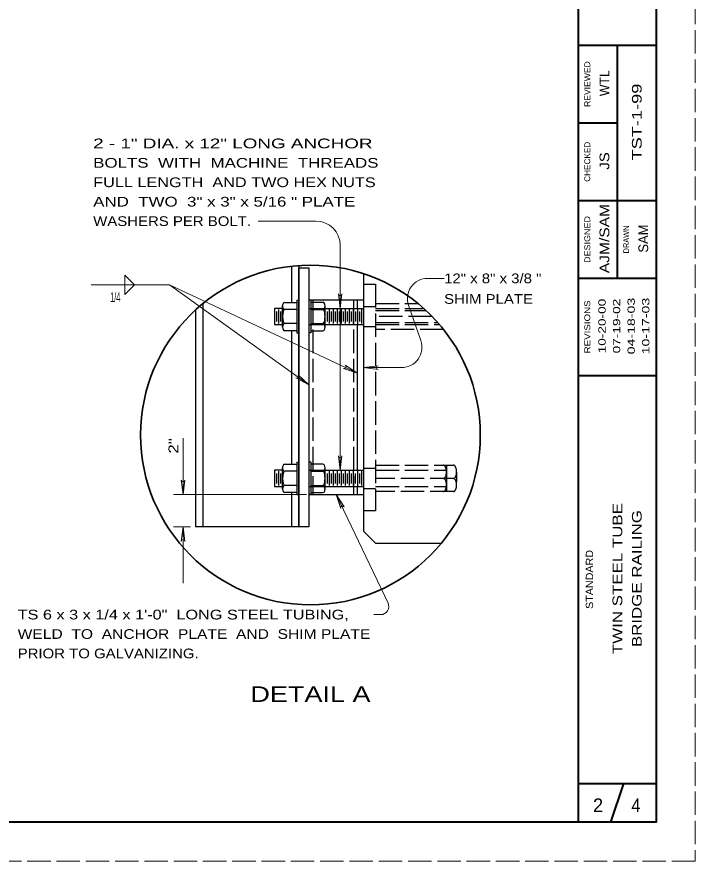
# Model space of a CAD drawing. Extents: x 1285 to 1427, y 1365 to 1427.
# Drawn here: x 1415.03 to 1426.67, y 1397.33 to 1411.82 of the extents above; entities that cross this region are included whole.
import ezdxf
from ezdxf.enums import TextEntityAlignment as Align

# ---------------------------------------------------------------- set-up
doc = ezdxf.new("R2010")
doc.units = 0
doc.header["$LTSCALE"] = 0.067
doc.linetypes.add('LONG_DASHED', pattern=[7.5, 6, -1.5])
for name, color, linetype, lineweight in [('1', 7, 'Continuous', 40), ('42', 7, 'Continuous', 25), ('44', 7, 'Continuous', 13)]:
    doc.layers.add(name, color=color, linetype=linetype, lineweight=lineweight)
doc.layers.add('41', color=7, linetype='Continuous')

msp = doc.modelspace()

# ---------------------------------------------------------------- linework, layer by layer
at = {"layer": '1'}
for p, q in [((1424.66667, 1398), (1424.66667, 1426)), ((1424.66667, 1411.33333), (1426, 1411.33333)), ((1425.33333, 1407.33333), (1425.33333, 1411.33333)), ((1424.66667, 1410), (1425.33333, 1410)), ((1424.66667, 1408.66667), (1426, 1408.66667)), ((1424.66667, 1407.33333), (1426, 1407.33333)), ((1424.66667, 1405.66667), (1426, 1405.66667)), ((1424.66667, 1398.66667), (1426, 1398.66667)), ((1425.22222, 1398), (1425.44444, 1398.66667))]:
    msp.add_line(p, q, dxfattribs=at)
at = {"layer": '1', "linetype": 'LONG_DASHED', "lineweight": 13}
msp.add_lwpolyline([(1381.33333, 1426.66667), (1426.66667, 1426.66667), (1426.66667, 1397.33333), (1381.33333, 1397.33333)], close=True, dxfattribs=at)
at = {"layer": '1'}
msp.add_lwpolyline([(1384, 1426), (1426, 1426), (1426, 1398), (1384, 1398)], close=True, dxfattribs=at)
at = {"layer": '42'}
for p, q in [((1419.74011, 1407.53967), (1419.74011, 1406.921)), ((1419.86656, 1407.54878), (1419.86656, 1403.067)), ((1418.22078, 1406.895), (1418.22078, 1403.067)), ((1419.62367, 1406.921), (1419.83211, 1406.921)), ((1419.83211, 1406.95567), (1419.83189, 1406.40033)), ((1419.83211, 1406.95567), (1419.86656, 1406.95567)), ((1420.97767, 1406.95589), (1420.04033, 1406.95589)), ((1420.07478, 1406.95567), (1420.04033, 1406.95567)), ((1420.07478, 1406.95567), (1420.075, 1406.40033)), ((1420.28322, 1406.921), (1420.07478, 1406.921)), ((1420.87367, 1406.81678), (1420.87367, 1406.95589)), ((1418.09433, 1406.78856), (1418.09433, 1403.067)), ((1419.48478, 1406.76478), (1419.48478, 1406.591)), ((1419.51944, 1406.79944), (1419.51944, 1406.55633)), ((1419.55411, 1406.76478), (1419.55411, 1406.591)), ((1419.589, 1406.49567), (1419.589, 1406.86033)), ((1419.83189, 1406.79944), (1419.62367, 1406.79944)), ((1420.075, 1406.79944), (1420.28322, 1406.79944)), ((1420.31789, 1406.49567), (1420.31789, 1406.86033)), ((1420.31789, 1406.81678), (1420.97767, 1406.81678)), ((1420.35278, 1406.76478), (1420.35278, 1406.591)), ((1420.38744, 1406.79944), (1420.38744, 1406.55633)), ((1420.42211, 1406.76478), (1420.42211, 1406.591)), ((1420.45678, 1406.79944), (1420.45678, 1406.55633)), ((1420.49144, 1406.76478), (1420.49144, 1406.591)), ((1420.52611, 1406.79944), (1420.52611, 1406.55633)), ((1420.56078, 1406.76478), (1420.56078, 1406.591)), ((1420.59544, 1406.79944), (1420.59544, 1406.55633)), ((1420.63011, 1406.76478), (1420.63011, 1406.591)), ((1420.66478, 1406.79944), (1420.66478, 1406.55633)), ((1420.69944, 1406.76478), (1420.69944, 1406.591)), ((1420.73411, 1406.79944), (1420.73411, 1406.55633)), ((1420.76878, 1406.76478), (1420.76878, 1406.591)), ((1420.80344, 1406.79944), (1420.80344, 1406.55633)), ((1420.83811, 1406.76478), (1420.83811, 1406.591)), ((1420.87278, 1406.79944), (1420.87278, 1406.55633)), ((1420.90744, 1406.76478), (1420.90744, 1406.591)), ((1420.94211, 1406.79944), (1420.94211, 1406.55633)), ((1419.83189, 1406.55633), (1419.62367, 1406.55633)), ((1420.075, 1406.55633), (1420.28322, 1406.55633)), ((1420.31789, 1406.539), (1420.97744, 1406.539)), ((1420.87367, 1404.039), (1420.87367, 1406.539)), ((1419.83189, 1406.435), (1419.62367, 1406.435)), ((1419.74011, 1406.435), (1419.74011, 1404.14322)), ((1419.83211, 1406.40033), (1419.86656, 1406.40033)), ((1420.07478, 1406.40033), (1420.04033, 1406.40033)), ((1420.075, 1406.435), (1420.28322, 1406.435)), ((1419.62367, 1404.14322), (1419.83211, 1404.14322)), ((1419.83211, 1404.17789), (1419.83189, 1403.62256)), ((1419.83211, 1404.17789), (1419.86656, 1404.17789)), ((1420.07478, 1404.17789), (1420.04033, 1404.17789)), ((1420.07478, 1404.17789), (1420.075, 1403.62256)), ((1420.28322, 1404.14322), (1420.07478, 1404.14322)), ((1419.48478, 1403.987), (1419.48478, 1403.81322)), ((1419.51944, 1404.02167), (1419.51944, 1403.77856)), ((1419.55411, 1403.987), (1419.55411, 1403.81322)), ((1419.589, 1403.71789), (1419.589, 1404.08256)), ((1419.83189, 1404.02167), (1419.62367, 1404.02167)), ((1420.075, 1404.02167), (1420.28322, 1404.02167)), ((1420.31789, 1403.71789), (1420.31789, 1404.08256)), ((1420.31789, 1404.039), (1420.97744, 1404.039)), ((1420.35256, 1403.987), (1420.35256, 1403.81322)), ((1420.38722, 1404.02167), (1420.38722, 1403.77856)), ((1420.42189, 1403.987), (1420.42189, 1403.81322)), ((1420.45656, 1404.02167), (1420.45656, 1403.77856)), ((1420.49122, 1403.987), (1420.49122, 1403.81322)), ((1420.52589, 1404.02167), (1420.52589, 1403.77856)), ((1420.56056, 1403.987), (1420.56056, 1403.81322)), ((1420.59522, 1404.02167), (1420.59522, 1403.77856)), ((1420.62989, 1403.987), (1420.62989, 1403.81322)), ((1420.66456, 1404.02167), (1420.66456, 1403.77856)), ((1420.69922, 1403.987), (1420.69922, 1403.81322)), ((1420.73389, 1404.02167), (1420.73389, 1403.77856)), ((1420.76856, 1403.987), (1420.76856, 1403.81322)), ((1420.80322, 1404.02167), (1420.80322, 1403.77856)), ((1420.83789, 1403.987), (1420.83789, 1403.81322)), ((1420.87256, 1404.02167), (1420.87256, 1403.77856)), ((1420.90722, 1403.987), (1420.90722, 1403.81322)), ((1420.94189, 1404.02167), (1420.94189, 1403.77856)), ((1419.83189, 1403.77856), (1419.62367, 1403.77856)), ((1420.075, 1403.77856), (1420.28322, 1403.77856)), ((1420.31789, 1403.76122), (1420.97744, 1403.76122)), ((1420.87367, 1403.62256), (1420.87367, 1403.76122)), ((1419.83189, 1403.65722), (1419.62367, 1403.65722)), ((1419.74011, 1403.65722), (1419.74011, 1403.067)), ((1419.83211, 1403.62256), (1419.86656, 1403.62256)), ((1420.07478, 1403.62256), (1420.04033, 1403.62256)), ((1420.075, 1403.65722), (1420.28322, 1403.65722)), ((1419.86656, 1403.067), (1418.09433, 1403.067))]:
    msp.add_line(p, q, dxfattribs=at)
at = {"layer": '42', "linetype": 'LONG_DASHED'}
for p, q in [((1420.10989, 1406.95589), (1420.10989, 1403.62256)), ((1420.80411, 1406.95589), (1420.80411, 1403.62256)), ((1421.18567, 1406.90389), (1421.90322, 1406.90389)), ((1420.04033, 1406.81678), (1420.31789, 1406.81678)), ((1420.87367, 1406.81678), (1420.87367, 1406.539)), ((1420.97744, 1406.85167), (1421.18567, 1406.85167)), ((1421.18567, 1406.817), (1422.01056, 1406.817)), ((1421.18567, 1406.78256), (1422.04656, 1406.78256)), ((1422.151, 1406.67811), (1421.18567, 1406.67811)), ((1420.04033, 1406.539), (1420.31789, 1406.539)), ((1420.97744, 1406.50456), (1421.18567, 1406.50456)), ((1421.18567, 1406.57411), (1422.25122, 1406.57411)), ((1421.18567, 1406.53922), (1422.27944, 1406.53922)), ((1422.34989, 1406.45233), (1421.18567, 1406.45233)), ((1421.18567, 1404.12611), (1422.52256, 1404.12611)), ((1422.401, 1404.12611), (1422.401, 1404.00478)), ((1420.04033, 1404.039), (1420.31789, 1404.039)), ((1420.87367, 1404.039), (1420.87367, 1403.76122)), ((1420.97744, 1404.07389), (1421.18567, 1404.07389)), ((1421.18567, 1404.03922), (1422.401, 1404.03922)), ((1422.57456, 1404.00478), (1422.57456, 1403.83856)), ((1422.52256, 1403.90033), (1421.18567, 1403.90033)), ((1420.04033, 1403.76122), (1420.31789, 1403.76122)), ((1420.97744, 1403.72678), (1421.18567, 1403.72678)), ((1421.18567, 1403.76144), (1422.401, 1403.76144)), ((1422.52256, 1403.67456), (1421.18567, 1403.67456))]:
    msp.add_line(p, q, dxfattribs=at)
at = {"layer": '42'}
msp.add_lwpolyline([(1419.86656, 1407.51144), (1420.04033, 1407.51144), (1420.04033, 1403.067), (1419.86656, 1403.067)], close=True, dxfattribs=at)
for points in [[(1420.97767, 1407.41322), (1420.97744, 1402.99744), (1421.18589, 1402.789), (1422.31433, 1402.789)], [(1420.04033, 1406.95589), (1420.04033, 1403.62256), (1420.97744, 1403.62256)], [(1419.589, 1406.81678), (1419.45011, 1406.81678), (1419.45011, 1406.539), (1419.589, 1406.539)], [(1419.589, 1404.039), (1419.45011, 1404.039), (1419.45011, 1403.76122), (1419.589, 1403.76122)]]:
    msp.add_lwpolyline(points, dxfattribs=at)
at = {"layer": '42', "linetype": 'LONG_DASHED'}
for points in [[(1420.97744, 1407.23367), (1421.18567, 1407.23367), (1421.18567, 1403.34478), (1420.97744, 1403.34478)], [(1422.401, 1404.00478), (1422.401, 1403.79633), (1422.401, 1403.67456)]]:
    msp.add_lwpolyline(points, dxfattribs=at)
at = {"layer": '42'}
for centre, major_axis, ratio, start_param, end_param in [((1419.62367, 1406.86033), (0, -0.06067), 0.571429, 3.14159265, 6.28318531), ((1420.28322, 1406.86033), (0, -0.06067), 0.571429, 6.28318531, 9.42477796), ((1419.62367, 1406.67789), (0, 0.12156), 0.285192, 6.28318531, 9.42477796), ((1420.28322, 1406.67789), (0, 0.12156), 0.285192, 3.14159265, 6.28318531), ((1419.62367, 1406.49567), (0, 0.06067), 0.571429, 6.28318531, 9.42477796), ((1420.28322, 1406.49567), (0, 0.06067), 0.571429, 3.14159265, 6.28318531), ((1419.62367, 1404.08256), (0, -0.06067), 0.571429, 3.14159265, 6.28318531), ((1420.28322, 1404.08256), (0, -0.06067), 0.571429, 6.28318531, 9.42477796), ((1419.62367, 1403.90011), (0, 0.12156), 0.285192, 6.28318531, 9.42477796), ((1420.28322, 1403.90011), (0, 0.12156), 0.285192, 3.14159265, 6.28318531), ((1419.62367, 1403.71789), (0, 0.06067), 0.571429, 6.28318531, 9.42477796), ((1420.28322, 1403.71789), (0, 0.06067), 0.571429, 3.14159265, 6.28318531)]:
    msp.add_ellipse(centre, major_axis=major_axis, ratio=ratio, start_param=start_param, end_param=end_param, dxfattribs=at)
at = {"layer": '42', "linetype": 'LONG_DASHED'}
for centre, start_param, end_param in [((1422.34889, 1406.56531), 6.28318531, 6.29883766), ((1422.34889, 1404.01328), 1.49443008, 3.14159265), ((1422.52259, 1404.01328), 1.49443008, 3.14159265), ((1422.34889, 1404.01328), 6.28318531, 7.77761538), ((1422.52259, 1404.01328), 6.28318531, 7.77761538), ((1422.34889, 1403.78754), 1.64880818, 3.14159265), ((1422.52259, 1403.78754), 1.64880818, 3.14159265), ((1422.34889, 1403.78754), 6.28318531, 7.93199349), ((1422.52259, 1403.78754), 6.28318531, 7.93199349)]:
    msp.add_ellipse(centre, major_axis=(0, -0.11287), ratio=0.461034, start_param=start_param, end_param=end_param, dxfattribs=at)
at = {"layer": '44'}
for p, q in [((1419.17056, 1408.31467), (1420.16111, 1408.31467)), ((1420.57778, 1407.898), (1420.57778, 1404.039)), ((1422.36089, 1407.33256), (1422.07844, 1407.33256)), ((1417.64811, 1407.22356), (1420.87367, 1405.70822)), ((1420.54656, 1407.06678), (1420.57778, 1406.81678)), ((1420.57778, 1406.81678), (1420.609, 1407.06678)), ((1421.75056, 1406.87111), (1421.96222, 1406.26356)), ((1420.63411, 1405.78622), (1420.87367, 1405.70822)), ((1420.87367, 1405.70822), (1420.66067, 1405.84278)), ((1421.22767, 1405.83333), (1420.97767, 1405.80211)), ((1419.81911, 1405.624), (1420.04033, 1405.50344)), ((1420.04033, 1405.50344), (1419.85556, 1405.67478)), ((1420.54656, 1404.289), (1420.57778, 1404.039)), ((1420.57778, 1404.039), (1420.609, 1404.289)), ((1417.85167, 1403.87256), (1417.88289, 1403.62256)), ((1419.99867, 1403.62256), (1417.71622, 1403.62256)), ((1420.50889, 1403.62256), (1421.39844, 1401.762)), ((1420.50889, 1403.62256), (1420.58856, 1403.38356)), ((1420.64489, 1403.41044), (1420.50889, 1403.62256)), ((1418.011, 1403.067), (1417.71622, 1403.067)), ((1417.88289, 1403.067), (1417.85167, 1402.817)), ((1417.88289, 1403.067), (1417.88289, 1402.10067)), ((1417.91411, 1402.817), (1417.88289, 1403.067)), ((1421.27311, 1401.56322), (1421.15611, 1401.56322))]:
    msp.add_line(p, q, dxfattribs=at)
msp.add_lwpolyline([(1416.881, 1407.22356), (1416.881, 1407.05689), (1417.04767, 1407.22356), (1416.881, 1407.39022)], close=True, dxfattribs=at)
for points in [[(1420.04033, 1405.50344), (1417.64811, 1407.22356), (1416.30533, 1407.22356)], [(1421.63433, 1405.80211), (1420.97767, 1405.80211), (1421.22767, 1405.77089)], [(1417.88289, 1404.58889), (1417.88289, 1403.62256), (1417.91411, 1403.87256)]]:
    msp.add_lwpolyline(points, dxfattribs=at)
at = {"layer": '44', "lineweight": 35}
msp.add_circle((1420.06806, 1404.645), 2.91384, dxfattribs=at)
at = {"layer": '44'}
for centre, radius, start, end in [((1420.16111, 1407.898), 0.41667, 0, 90), ((1422.07845, 1406.98533), 0.34722, 90, 199.20923), ((1420.57778, 1407.06678), 0.03122, 180, 0), ((1421.63434, 1406.14933), 0.34722, 270, 19.20915), ((1420.64739, 1405.81452), 0.03122, 244.83634, 64.83634), ((1421.22767, 1405.80211), 0.03122, 90, 270), ((1419.83736, 1405.64939), 0.03122, 234.28223, 54.28223), ((1420.57778, 1404.289), 0.03122, 180, 0), ((1417.88293, 1403.87256), 0.03122, 180, 0), ((1420.61672, 1403.39701), 0.03122, 25.5522, 205.5522), ((1417.88293, 1402.817), 0.03122, 0, 180), ((1421.2731, 1401.70211), 0.13889, 270, 25.5522)]:
    msp.add_arc(centre, radius, start, end, dxfattribs=at)

# ---------------------------------------------------------------- texts
at = {"layer": '1'}
for s, height, width, p in [('REVIEWED', 0.1, 1.1, (1424.86667, 1410.66667)), ('CHECKED', 0.1, 1.05, (1424.86667, 1409.33339)), ('DESIGNED', 0.1, 1.15, (1424.86667, 1408)), ('DRAWN', 0.1, 0.95, (1425.53333, 1408)), ('REVISIONS', 0.1, 1.25, (1424.86667, 1406.50011)), ('STANDARD', 0.125, 1.1, (1424.91667, 1402.16672))]:
    msp.add_text(s, height=height, rotation=90, dxfattribs=dict(at, width=width)).set_placement(p, align=Align.CENTER)
at = {"layer": '41'}
for s, width, p in [('2 - 1" DIA. x 12" LONG ANCHOR', 1.45, (1416.34122, 1409.56467)), ('BOLTS  WITH  MACHINE  THREADS', 1.3, (1416.34122, 1409.23133)), ('FULL LENGTH  AND TWO HEX NUTS', 1.25, (1416.34122, 1408.898)), ('AND  TWO  3" x 3" x 5/16 " PLATE', 1.3, (1416.34122, 1408.56467)), ('WASHERS PER BOLT.', 1.15, (1416.34122, 1408.23133))]:
    msp.add_text(s, height=0.1667, dxfattribs=dict(at, width=width)).set_placement(p)
for s, width, p in [('10-20-00', 1.4, (1425.132, 1406.51433)), ('07-19-02', 1.4, (1425.382, 1406.51433)), ('04-18-03', 1.45, (1425.632, 1406.51433)), ('10-17-03', 1.45, (1425.882, 1406.51433))]:
    msp.add_text(s, height=0.125, rotation=90, dxfattribs=dict(at, width=width)).set_placement(p, align=Align.CENTER)
at = {"layer": '44'}
for s, width, p in [('WTL', 0.95, (1425.19444, 1410.68222)), ('TST-1-99', 1.4, (1425.75, 1410.01428)), ('JS', 1.15, (1425.19444, 1409.34767)), ('AJM/SAM', 1.2, (1425.19444, 1408.0155)), ('TWIN STEEL TUBE', 1.3, (1425.41667, 1402.181)), ('BRIDGE RAILING', 1.3, (1425.75, 1402.18094))]:
    msp.add_text(s, height=0.1667, rotation=90, dxfattribs=dict(at, width=width)).set_placement(p, align=Align.CENTER)
msp.add_text('SAM', height=0.1667, rotation=90, dxfattribs=at).set_placement((1425.86111, 1408.01561), align=Align.CENTER)
for s, width, p in [('12" x 8" x 3/8 "', 1.15, (1422.36089, 1407.24922)), ('SHIM PLATE', 1.15, (1422.36089, 1406.89589)), ('TS 6 x 3 x 1/4 x 1\'-0"  LONG STEEL TUBING,', 1.25, (1415.04544, 1401.47989)), ('WELD  TO  ANCHOR  PLATE  AND  SHIM PLATE', 1.2, (1415.04544, 1401.14656)), ('PRIOR TO GALVANIZING.', 1.15, (1415.04544, 1400.81322))]:
    msp.add_text(s, height=0.1667, dxfattribs=dict(at, width=width)).set_placement(p)
at = {"layer": '44', "width": 0.55}
msp.add_text('1/4', height=0.1667, dxfattribs=at).set_placement((1416.80756, 1406.92522), align=Align.RIGHT)
at = {"layer": '44', "width": 1.3}
msp.add_text('2"', height=0.1667, rotation=90, dxfattribs=at).set_placement((1417.79978, 1404.58889), align=Align.RIGHT)
at = {"layer": '44'}
for s, height, width, p in [('DETAIL A', 0.2667, 1.3, (1420.06817, 1400.06467)), ('4', 0.2333, 0.9, (1425.65178, 1398.17478))]:
    msp.add_text(s, height=height, dxfattribs=dict(at, width=width)).set_placement(p, align=Align.CENTER)
msp.add_text('2', height=0.2333, dxfattribs=at).set_placement((1425.002, 1398.17478), align=Align.CENTER)

doc.saveas('drawing.dxf')
